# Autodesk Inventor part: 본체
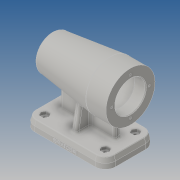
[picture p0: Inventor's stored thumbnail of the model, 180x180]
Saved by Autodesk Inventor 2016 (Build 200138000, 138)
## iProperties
Created: 2017-01
Part Number: 본체
Material: Generic
Document SubType Name: Modeling
Designer: Administrator
Density: 1 g/cm^3
Appearance: Default
Author: Administrator
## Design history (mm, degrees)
sketch "스케치1"
  geometry: L1 (-42, -35)-(42, -35); L2 (56, -21)-(56, 21); L3 (42, 35)-(-42, 35); L4 (-56, 21)-(-56, -21); L5 (-56, -35)-(56, 35); L6 (56, -35)-(-56, 35); A1 r 14 centre (-42, 21) between (-42, 35) and (-56, 21); A2 r 14 centre (42, 21) between (56, 21) and (42, 35); A3 r 14 centre (42, -21) between (42, -35) and (56, -21); A4 r 14 centre (-42, -21) between (-56, -21) and (-42, -35); 1 further point
  constraints: 12 end point, 8 point on circle, 8 point on line, 8 tangent, 4 centre point, 3 equal radius, 2 midpoint, 2 parallel, 1 horizontal, 1 perpendicular
  dimensions: "d0" = 112 distance of L5.end L6.end; "d1" = 70 distance of L6.start L5.end; "d2" = 14 radius of A1
extrude "돌출1" new body sketch "스케치1" distance "d3" = 7; taper "d4" = 0 deg
sketch "스케치2"
  geometry: L1 (-56, 21)-(-56, -21) reference; L2 (-42, -35)-(42, -35) reference; L3 (56, -21)-(56, 21) reference; L4 (42, 35)-(-42, 35) reference; L5 (-42, -35)-(42, -35); L6 (56, -21)-(56, 21); L7 (42, 35)-(-42, 35); L8 (-56, 21)-(-56, -21); L9 (-56, -35)-(56, 35); L10 (56, -35)-(-56, 35); A1 r 14 centre (-42, -21) between (-56, -21) and (-42, -35) reference; A2 r 14 centre (42, -21) between (42, -35) and (56, -21) reference; A3 r 14 centre (42, 21) between (56, 21) and (42, 35) reference; A4 r 14 centre (-42, 21) between (-42, 35) and (-56, 21) reference; A5 r 14 centre (-42, 21) between (-42, 35) and (-56, 21); A6 r 14 centre (42, 21) between (56, 21) and (42, 35); A7 r 14 centre (42, -21) between (42, -35) and (56, -21); A8 r 14 centre (-42, -21) between (-56, -21) and (-42, -35); 1 further point
  constraints: 12 end point, 8 point on circle, 8 point on line, 8 tangent, 4 centre point, 3 equal radius, 2 midpoint, 2 parallel, 1 horizontal, 1 perpendicular
  dimensions: "d5" = 112 distance of L9.end L10.end; "d6" = 70 distance of L10.end L9.start; "d7" = 14 radius of A5
extrude "돌출2" join sketch "스케치2" distance "d8" = 7; taper "d9" = -15 deg
sketch "스케치3"
  geometry: L1 (56, 74)-(-56, 74); L2 (-42, 0)-(42, 0) reference; L3 (56, 0)-(56, 7) reference; L4 (-56, 0)-(-56, 7) reference; L5 (-56, 74)-(-56, 108); L6 (-56, 108)-(-28, 108); L7 (-28, 108)-(52.27, 98.144); L8 (56, 74)-(-24, 74); A1 r 80 centre (-24, 74) between (56, 74) and (52.27, 98.144); 3 further points
  constraints: 10 end point, 2 midpoint, 2 point on circle, 1 centre point, 1 coincident, 1 horizontal, 1 perpendicular, 1 point on line, 1 vertical, 1 vertical alignment
  dimensions: "d10" = 74 distance between parallel lines of L1 L2; "d11" = 112 distance of L1.start L1.end; "d13" = 80 distance of L1.start L8.end; "d14" = 7 deg angle of L6 L7; "d15" = 68 diameter of L6 L1; "d16" = 28 distance from line of L6.end L5
revolve "회전1" sketch "스케치3" stored, may be unused: angle "d17" = 90 deg
sketch "스케치4"
  geometry: L1 (56, 0)-(42, 0) reference; L2 (-42, 0)-(42, 0) reference; L3 (-56, 0)-(-42, 0) reference; L4 (-42, 0)-(-42, 7) reference; L5 (-56, 7)-(-42, 7) reference; L6 (-56, 0)-(-56, 7) reference; L7 (-42, 0)-(-56, 0) reference; L8 (38, 0)-(38, 73); L9 (-38, 0)-(-38, 73); L10 (-38, 73)-(38, 73); L11 (56, 0)-(56, 7) reference; 1 further point
  constraints: 6 end point, 2 point on line, 2 vertical, 1 perpendicular
  dimensions: "d18" = 18 distance between parallel lines of L8 L11; "d19" = 18 distance between parallel lines of L6 L9; "d20" = 73 distance between parallel lines of L2 L10
extrude "돌출3" join sketch "스케치4" stored distance "d21" = 8; taper "d22" = 0 deg
sketch "스케치5"
  geometry: L1 (-33.124, 14)-(-21, 14) reference; L2 (-21, 14)-(21, 14) reference; L3 (21, 14)-(33.124, 14) reference; L4 (-23, 14)-(-14.184, 64); L5 (-14.184, 64)-(14.184, 64); L6 (14.184, 64)-(23, 14); L7 (35, 0)-(35, 7) reference; L8 (-35, 0)-(-35, 7) reference; 1 further point
  constraints: 6 end point, 2 point on line, 1 horizontal
  dimensions: "d23" = 12 horizontal distance of L7.start L6.end; "d24" = 12 horizontal distance of L4.start L8.start; "d25" = 100 deg angle of L1 L4; "d26" = 100 deg angle of L3 L6; "d27" = 50 distance between parallel lines of L2 L5
extrude "돌출4" join sketch "스케치5" stored distance "d28" = 8; taper "d29" = 0 deg
sketch "스케치6"
  geometry: L1 (-56, 40)-(-56, 108) reference; L2 (-56, 74)-(56, 74); L3 (-56, 95)-(-41, 95); L4 (-41, 95)-(-41, 98); L5 (-41, 98)-(13, 98); L6 (13, 98)-(13, 95); L7 (13, 95)-(25, 95); L8 (25, 95)-(25, 91.5); L9 (25, 91.5)-(43, 91.5); L10 (43, 91.5)-(43, 90); L11 (43, 90)-(47, 90); L12 (47, 90)-(47, 84.5); L13 (47, 84.5)-(50, 84.5); L14 (50, 84.5)-(50, 74); A1 r 80 centre (-24, 74) between (52.27, 49.856) and (52.27, 98.144) reference; 1 further point
  constraints: 26 end point, 8 perpendicular, 2 horizontal, 2 point on line, 1 midpoint, 1 parallel, 1 point on circle, 1 vertical
  dimensions: "d30" = 42 diameter of L3 L2; "d31" = 48 diameter of L5 L2; "d32" = 42 diameter of L7 L2; "d33" = 35 diameter of L9 L2; "d34" = 32 diameter of L11 L2; "d35" = 21 diameter of L13 L2; "d36" = 15 distance between parallel lines of L1 L4; "d37" = 4 distance between parallel lines of L10 L12; "d38" = 12 distance between parallel lines of L6 L8; "d39" = 18 distance between parallel lines of L10 L8; "d40" = 3 distance between parallel lines of L12 L14; "d41" = 54 distance of L4.end L5.end
revolve "회전2" sketch "스케치6" stored, may be unused: angle "d42" = 90 deg
sketch "스케치7"
  geometry: C1 r 21 at (0, 0) reference; 2 further points
  constraints: 1 horizontal alignment
  dimensions: "d43" = 26 distance of point (-26, 0) C1.centre
hole "구멍1" sketch "스케치7" at (-26, 0) diameter "d44" = 3.242; stored, may be unused: countersink angle "d48" = 90 deg, drill point angle "d50" = 118 deg; dims "d45" = 8, "d46" = 4, "d47" = 2, "d49" = 11
sketch "스케치8"
  geometry: L1 (98, 0)-(98, 7) reference; 2 further points
  constraints: 1 other
  dimensions: "d54" = 4 distance of point (42, 0) point (42, 4); "d55" = 56 distance from line of point (42, 4) L1
feature "엠보싱1" sketch "스케치8" dims "d0" = 112, "d1" = 70, "d2" = 14, "d56" = 0.5, "d57" = 0
sketch "스케치9"
  geometry: L1 (-36.226, 21)-(-39.113, 16); L2 (-39.113, 16)-(-44.887, 16); L3 (-44.887, 16)-(-47.774, 21); L4 (-47.774, 21)-(-44.887, 26); L5 (-44.887, 26)-(-39.113, 26); L6 (-39.113, 26)-(-36.226, 21); A1 r 12.124 centre (-42, 21) between (-42, 33.124) and (-54.124, 21) reference; 2 further points
  constraints: 12 end point, 1 coincident, 1 horizontal alignment, 13 other
  dimensions: "d58" = 10 distance between parallel lines of L5 L2
extrude "돌출5" cut sketch "스케치9" distance "d59" = 4; taper "d60" = 0 deg
sketch "스케치10"
  geometry: L1 (-47.774, 21)-(-36.226, 21); 2 further points
  constraints: 2 end point, 1 horizontal, 1 midpoint
hole "구멍2" sketch "스케치10" at (-42, 21) diameter "d61" = 5; stored, may be unused: countersink angle "d65" = 90 deg, drill point angle "d67" = 118 deg; dims "d62" = 8, "d63" = 4, "d64" = 2, "d66" = 11
fillet "모깎기1" dims "d68" = 0.3
fillet "모깎기2" dims "d69" = 3
fillet "모깎기3" dims "d70" = 1
fillet "모깎기4" dims "d71" = 3
fillet "모깎기5" dims "d72" = 3
fillet "모깎기6" dims "d73" = 3
chamfer "모따기1" distance "d74" = 1; stored, may be unused: second distance "d75" = 2, angle "d76" = 45 deg
node "솔리드1"
pattern_circular "원형 패턴1" dims angle "d52" = 360 deg
mirror "대칭1"
mirror "대칭2"
node "투영된 루프1"
